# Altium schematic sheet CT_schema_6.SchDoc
size 218 x 258 mm
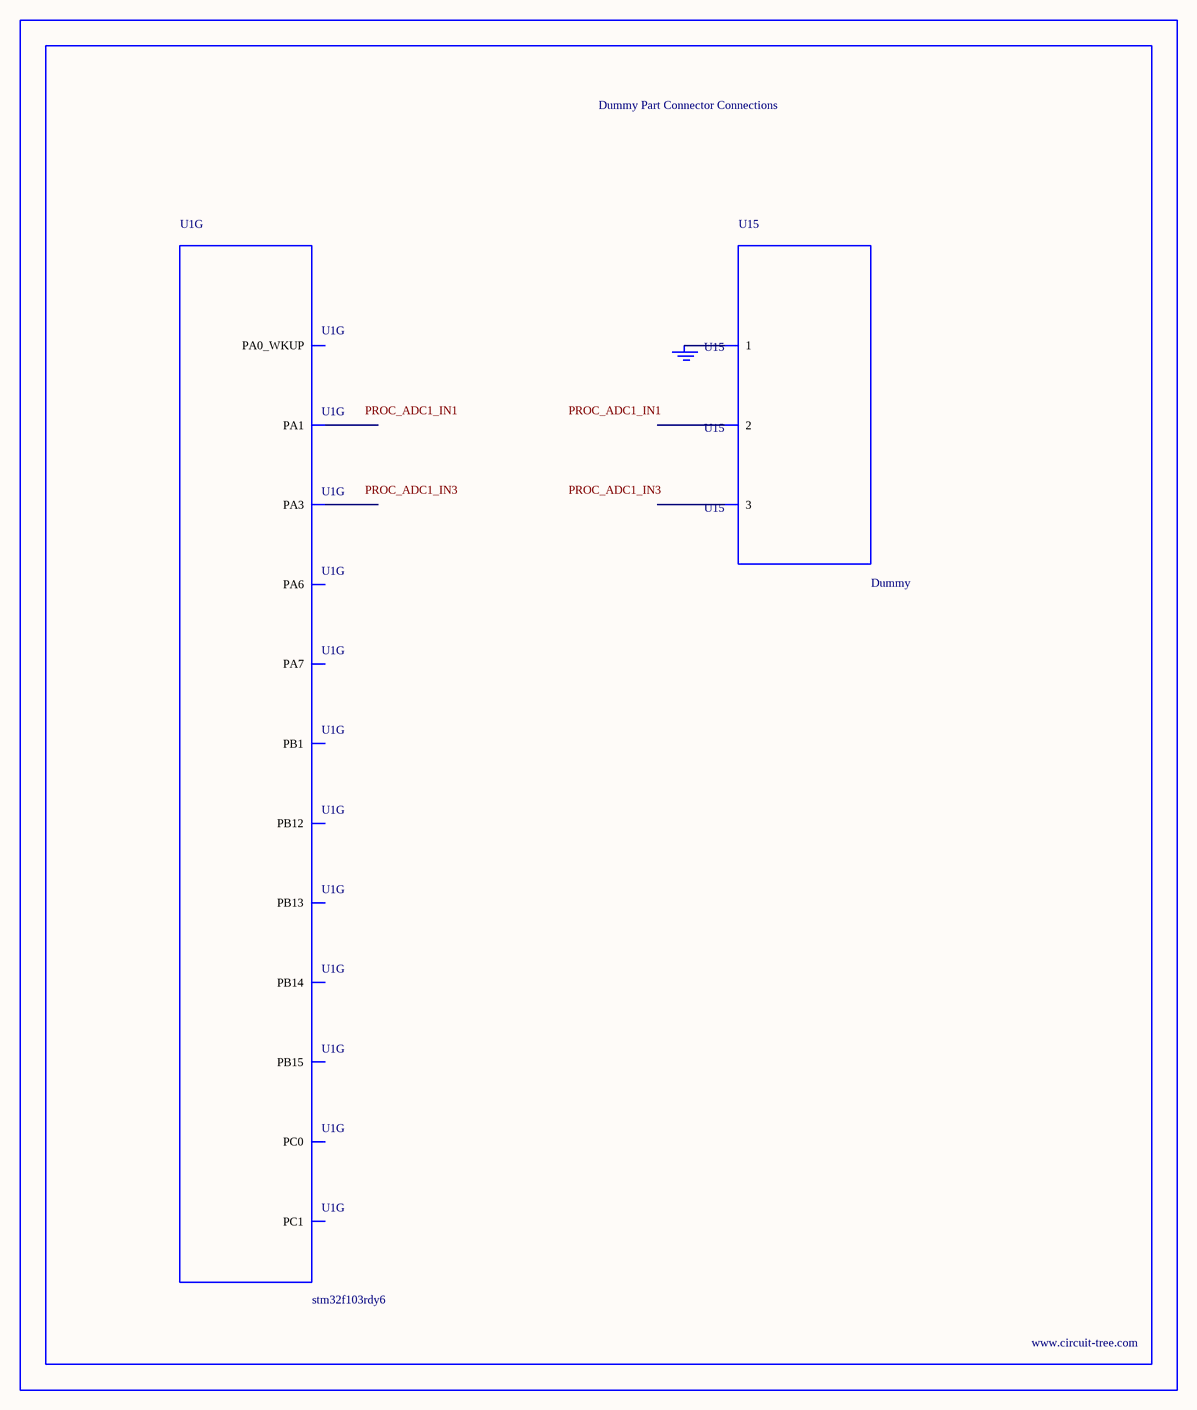
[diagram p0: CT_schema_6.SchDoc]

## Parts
BORDER5  (no value)
GND_INSTANCE_5_0  (no value)
U1  stm32f103rdy6  [WLCSP64]  (part G of 7)
U15  Dummy  [DUMMY_PACKAGE_181]

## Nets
NetGND_INSTANCE_5_0_0: GND_INSTANCE_5_0.0(GND) U15.1

Not connected (* = marked no-connect by the designer): U1 E6(PA1) E8(PC0) F1(PB15) F2(PB14) F4(PB1) F6(PA0_WKUP) F8(PC1) G1(PB13) G2(PB12) G4(PA7) G5(PA6) G7(PA3); U15 2 3

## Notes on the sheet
- Labels drawn without touching a wire or pin: PROC_ADC1_IN1, PROC_ADC1_IN3

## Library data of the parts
BORDER5 = BORDER_PAGE5
GND_INSTANCE_5_0 = GND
